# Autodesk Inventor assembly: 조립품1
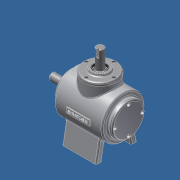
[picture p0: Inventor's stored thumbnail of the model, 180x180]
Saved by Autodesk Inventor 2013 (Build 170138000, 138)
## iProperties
Created: 2015-01
Part Number: 조립품1
Document SubType Name: Assembly
Designer: hanacad21
Author: hanacad21
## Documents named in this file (14)
- C:\Documents and Settings\hanacad21\바탕 화면\450106V1018\조립품1.iam
- C:\Documents and Settings\hanacad21\바탕 화면\450106V1018\본체.ipt
- C:\Documents and Settings\hanacad21\바탕 화면\450106V1018\커버.ipt
- C:\Documents and Settings\hanacad21\바탕 화면\450106V1018\커버2.ipt
- C:\Documents and Settings\hanacad21\바탕 화면\450106V1018\서브 축.ipt
- 서브 축.ipt
- C:\Documents and Settings\hanacad21\바탕 화면\450106V1018\메인 축.ipt
- 메인 축.ipt
- C:\Documents and Settings\hanacad21\바탕 화면\450106V1018\서브 베벨기어.ipt
- C:\Documents and Settings\hanacad21\바탕 화면\450106V1018\메인 베벨기어.ipt
- C:\Documents and Settings\hanacad21\바탕 화면\450106V1018\베어링 6203.ipt
- C:\Documents and Settings\hanacad21\바탕 화면\450106V1018\오일실.ipt
- C:\Documents and Settings\hanacad21\바탕 화면\450106V1018\키 5x5.ipt
- C:\Documents and Settings\hanacad21\바탕 화면\450106V1018\키 4x4.ipt
